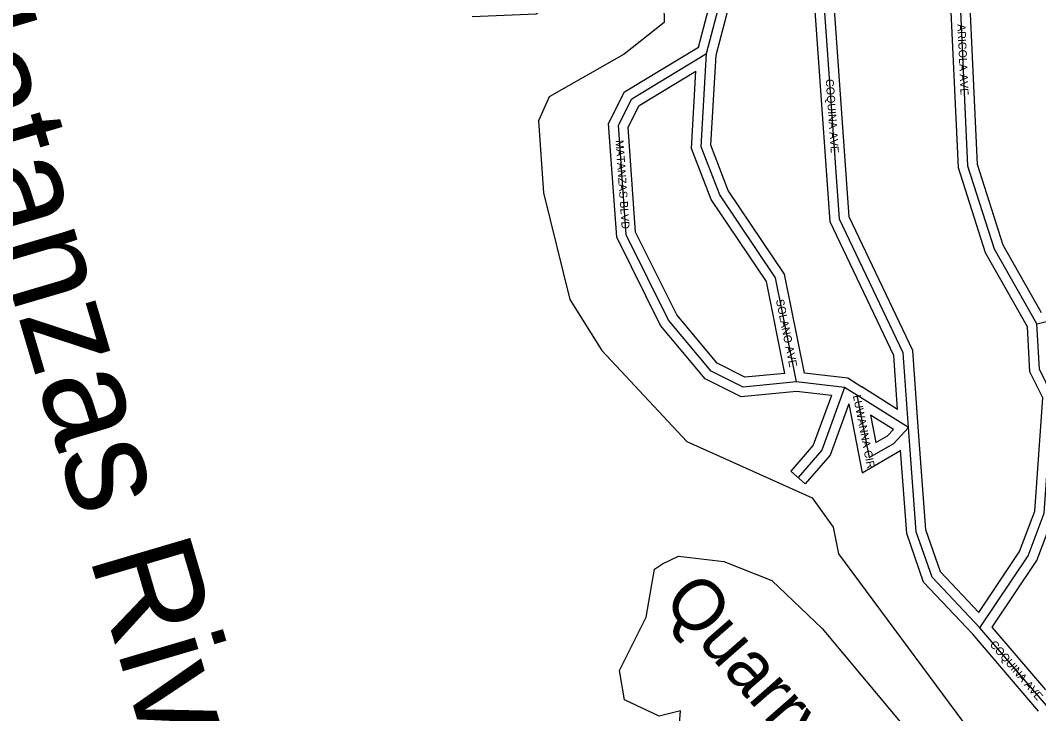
# Model space of a CAD drawing. Extents: x 418523 to 616617, y 1878279 to 2196743.
# Drawn here: x 559594 to 562775, y 2017206 to 2019372 of the extents above; entities that cross this region are included whole.
import ezdxf

# ---------------------------------------------------------------- set-up
doc = ezdxf.new("R2010")
doc.units = 0
for name, color, linetype in [('Level 31', 7, 'Continuous'), ('Level 32', 7, 'Continuous'), ('Level 34', 7, 'Continuous'), ('Level 41', 7, 'Continuous'), ('Level 5', 7, 'Continuous')]:
    doc.layers.add(name, color=color, linetype=linetype)

msp = doc.modelspace()

# ---------------------------------------------------------------- linework, layer by layer
at = {"layer": 'Level 31'}
for p, q in [((562769.316, 2018424.016), (563102.923, 2018506.444)), ((562168.564, 2018225.541), (562018.387, 2018242.656)), ((562206.85, 2018201.441), (562168.564, 2018225.541)), ((562368.22, 2018100.294), (562206.85, 2018201.441)), ((562322, 2018050.739), (562368.22, 2018100.294)), ((562799.24, 2017231.861), (562591.636, 2017474.226))]:
    msp.add_line(p, q, dxfattribs=at)
for points in [[(561737.705, 2019268.903), (561805.238, 2019527.292), (561763.835, 2019693.956)], [(562368.22, 2018100.294), (562352.02, 2018333.441), (562153.115, 2018751.071), (562105.091, 2019426.149), (561997.18, 2019610.076)], [(562769.316, 2018424.016), (562636.49, 2018657.826), (562553.801, 2018916.601), (562522.294, 2019608.727)], [(562018.387, 2018242.656), (561851.647, 2018226.721), (561751.629, 2018276.801), (561618.933, 2018435.699), (561486.2, 2018702.606), (561462.046, 2019044.509), (561504.094, 2019127.679), (561737.705, 2019268.903)], [(562018.387, 2018242.656), (561952.67, 2018567.937), (561778.399, 2018826.95), (561720.474, 2018977.291), (561737.705, 2019268.903)], [(562591.636, 2017474.226), (562742.115, 2017698.946), (562792.529, 2017832.281), (562818.499, 2018198.785), (562777.195, 2018282.533), (562769.316, 2018424.016)], [(562168.564, 2018225.541), (562097.07, 2018029.349), (562023.327, 2017944.441)], [(562206.85, 2018201.441), (562245.33, 2018006.057), (562322, 2018050.739)], [(562591.636, 2017474.226), (562441.82, 2017633.165), (562392.425, 2017774.756), (562368.22, 2018100.294)]]:
    msp.add_lwpolyline(points, dxfattribs=at)
at = {"layer": 'Level 32'}
for p, q in [((562178.758, 2018254.574), (562043.473, 2018269.991)), ((562222.832, 2018226.831), (562178.758, 2018254.574)), ((562127.343, 2018200.044), (562018.114, 2018212.491)), ((562334.205, 2018157.021), (562222.783, 2018226.861)), ((562321.492, 2018094.176), (562249.69, 2018139.182)), ((562303.078, 2018074.435), (562321.491, 2018094.176)), ((562340.919, 2018027.04), (562343.387, 2018029.681)), ((562045.977, 2017924.769), (562000.677, 2017964.115)), ((562796.866, 2017280.749), (562629.233, 2017476.45)), ((562774.851, 2017214.217), (562569.317, 2017454.166))]:
    msp.add_line(p, q, dxfattribs=at)
for points in [[(561711.76, 2019288.274), (561774.279, 2019527.48), (561733.408, 2019692.004)], [(561767.479, 2019264.179), (561836.197, 2019527.104), (561806.476, 2019646.746)], [(562398.148, 2018102.373), (562381.554, 2018341.201), (562182.638, 2018758.853), (562134.518, 2019435.278), (562017.557, 2019634.63)], [(562739.755, 2018415.319), (562608.863, 2018645.721), (562524.012, 2018911.26), (562492.662, 2019599.958)], [(562784.178, 2018458.59), (562664.117, 2018669.931), (562583.59, 2018921.941), (562551.926, 2019617.495)], [(562334.205, 2018157.021), (562322.485, 2018325.681), (562123.592, 2018743.289), (562075.664, 2019417.021), (561976.805, 2019585.52)], [(562018.114, 2018212.492), (561845.922, 2018196.036), (561732.608, 2018252.773), (561593.643, 2018419.179), (561456.692, 2018694.566), (561431.536, 2019050.656), (561481.205, 2019148.899), (561711.76, 2019288.274)], [(562043.473, 2018269.991), (561980.894, 2018579.731), (561805.178, 2018840.891), (561750.806, 2018982.011), (561767.48, 2019264.178)], [(561982.388, 2018269.352), (561857.373, 2018257.406), (561770.65, 2018300.828), (561644.223, 2018452.219), (561515.706, 2018710.646), (561492.556, 2019038.363), (561526.983, 2019106.46), (561704.39, 2019213.706)], [(561982.388, 2018269.352), (561924.446, 2018556.145), (561751.62, 2018813.008), (561690.142, 2018972.572), (561704.39, 2019213.706)], [(562587.651, 2017522.191), (562715.27, 2017712.777), (562762.914, 2017838.784), (562787.999, 2018192.801), (562747.581, 2018274.753), (562739.754, 2018415.318)], [(562629.233, 2017476.45), (562768.96, 2017685.116), (562822.144, 2017825.78), (562848.999, 2018204.767), (562806.81, 2018290.312), (562800.654, 2018400.856)], [(562127.342, 2018200.044), (562070.782, 2018044.833), (562000.677, 2017964.115)], [(562181.69, 2018173.936), (562123.359, 2018013.865), (562045.977, 2017924.769)], [(562181.69, 2018173.936), (562224.036, 2017958.925), (562340.919, 2018027.04)], [(562249.689, 2018139.181), (562266.625, 2018053.191), (562303.078, 2018074.435)], [(562587.651, 2017522.191), (562468.04, 2017649.087), (562422.05, 2017780.914), (562398.138, 2018102.518)], [(562569.317, 2017454.166), (562415.6, 2017617.242), (562362.799, 2017768.597), (562343.388, 2018029.681)]]:
    msp.add_lwpolyline(points, dxfattribs=at)
at = {"layer": 'Level 5'}
for points in [[(561004.763, 2019384.707), (561204.867, 2019392.38), (561288.428, 2019450.482), (561405.757, 2019641.858), (561423.313, 2019916.885), (561523.614, 2019999.928), (561581.995, 2020008.069), (561631.887, 2019966.218), (561597.82, 2019749.603), (561604.947, 2019366.104), (561479.575, 2019266.461), (561245.703, 2019133.825), (561212.133, 2019058.932)], [(561212.133, 2019058.932), (561228.088, 2018833.787), (561310.375, 2018500.071), (561409.89, 2018341.348), (561675.732, 2018057.035)], [(561675.732, 2018057.035), (562066.995, 2017880.726), (562133.387, 2017788.795), (562149.77, 2017705.373), (562539.878, 2017178.936), (562639.363, 2017003.542), (562696.77, 2016711.576)], [(561599.467, 2017673.826), (561649.588, 2017698.666), (561791.241, 2017681.538), (561941.095, 2017622.688), (562098.992, 2017472.116), (562447.788, 2017054.181), (562421.793, 2016754.144), (562471.655, 2016703.964), (562528.892, 2016353.666), (562570.583, 2016353.537), (562579.47, 2016528.571), (562696.77, 2016711.576)], [(561462.533, 2016573.849), (561505.318, 2016915.507), (561647.658, 2017106.783), (561656.356, 2017215.126), (561589.595, 2017198.685), (561481.391, 2017249.024), (561465.01, 2017340.796), (561548.929, 2017507.261), (561574.396, 2017657.215), (561599.467, 2017673.826)]]:
    msp.add_lwpolyline(points, dxfattribs=at)

# ---------------------------------------------------------------- texts
at = {"layer": 'Level 34'}
for s, rotation, p in [('ARICOLA AVE', 272.6055, (562521.092, 2019360.262)), ('COQUINA AVE', 274.068044, (562109.495, 2019188.1)), ('MATANZAS BLVD', 274.039828, (561452.833, 2018997.565)), ('SOLANO AVE', 281.420828, (561954.004, 2018498.218)), ('LUWANNA CIR', 281.140719, (562194.472, 2018199.606)), ('COQUINA AVE', 310.581669, (562620.482, 2017421.338))]:
    msp.add_text(s, height=25, rotation=rotation, dxfattribs=at).set_placement(p)
at = {"layer": 'Level 41'}
for s, height, rotation, p in [('Matanzas River', 320, 286.452267, (559248.603, 2019591.812)), ('Quarry Creek', 160, 311.234106, (561597.21, 2017555.883))]:
    msp.add_text(s, height=height, rotation=rotation, dxfattribs=at).set_placement(p)

doc.saveas('drawing.dxf')
